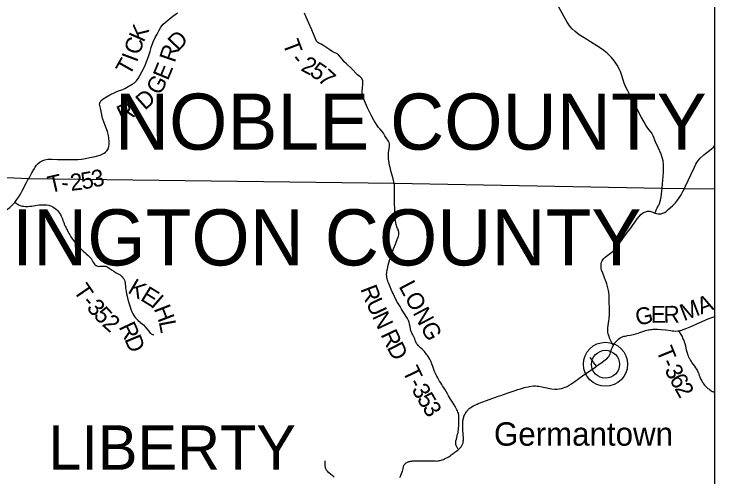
# Model space of a CAD drawing. Extents: x -10.5 to 40.6, y -3.2 to 22.
# Drawn here: x -6.111 to -3.744, y 15.878 to 17.441 of the extents above; entities that cross this region are included whole.
import ezdxf

# ---------------------------------------------------------------- set-up
doc = ezdxf.new("R2010")
doc.units = 0
for name, color, linetype in [('GM_X_County_Road', 7, 'Continuous'), ('GM_X_County_Road_Text', 7, 'Continuous'), ('GM_X_County_Text', 7, 'Continuous'), ('GM_X_Township_Road', 7, 'Continuous'), ('GM_X_Township_Road_Text', 7, 'Continuous'), ('GM_X_Township_Text', 7, 'Continuous'), ('GM_X_Unincorporated', 7, 'Continuous'), ('GM_X_Unincorporated_Location', 7, 'Continuous'), ('GM_X_Unincorporated_Text', 7, 'Continuous')]:
    doc.layers.add(name, color=color, linetype=linetype)

msp = doc.modelspace()

# ---------------------------------------------------------------- linework, layer by layer
at = {"layer": 'GM_X_County_Road'}
for points in [[(-3.9229, 16.8524), (-3.9187, 16.9064), (-3.9181, 16.9318), (-3.9195, 16.9446), (-3.9213, 16.9525), (-3.9266, 16.9678), (-3.9363, 16.9905), (-3.9448, 17.0094), (-3.9535, 17.0299), (-3.9578, 17.0378), (-3.9626, 17.0445), (-3.9708, 17.0557), (-3.9776, 17.0657), (-3.9852, 17.0778), (-3.9923, 17.0907), (-4.0218, 17.148), (-4.0293, 17.1627), (-4.0388, 17.1811), (-4.0461, 17.1958), (-4.051, 17.2067), (-4.0546, 17.2183), (-4.0611, 17.2399), (-4.0636, 17.247), (-4.0669, 17.2535), (-4.0749, 17.2681), (-4.0839, 17.2813), (-4.0938, 17.2934), (-4.1099, 17.3092), (-4.1247, 17.3213), (-4.1432, 17.3335), (-4.1652, 17.3472), (-4.186, 17.3599), (-4.2034, 17.3705), (-4.2103, 17.3758), (-4.2167, 17.3811), (-4.2264, 17.3905), (-4.2341, 17.3999), (-4.2431, 17.4125), (-4.2536, 17.4307), (-4.2776, 17.4736)], [(-3.8479, 16.8511), (-3.8436, 16.8597), (-3.8262, 16.8978), (-3.8138, 16.9239), (-3.8088, 16.9339), (-3.8054, 16.9396), (-3.8005, 16.9469), (-3.7942, 16.9542), (-3.7825, 16.9647), (-3.7577, 16.984), (-3.749, 16.9916), (-3.7445, 16.9965)], [(-3.9472, 16.7684), (-3.9468, 16.7693), (-3.9429, 16.7783), (-3.9414, 16.7819), (-3.9392, 16.7866), (-3.9379, 16.7892), (-3.9362, 16.7922), (-3.9347, 16.7951), (-3.9334, 16.7977), (-3.932, 16.8013), (-3.9312, 16.8036), (-3.9305, 16.8059), (-3.9288, 16.8118), (-3.9265, 16.8221), (-3.9248, 16.8325), (-3.9238, 16.8436), (-3.9229, 16.8524)], [(-3.9472, 16.7684), (-3.9418, 16.767), (-3.9364, 16.7662), (-3.9309, 16.7661), (-3.9267, 16.7665), (-3.9214, 16.7678), (-3.9174, 16.7692), (-3.9142, 16.7709), (-3.9087, 16.7747), (-3.9021, 16.7802), (-3.8881, 16.7934), (-3.8782, 16.8037), (-3.8706, 16.8126), (-3.8651, 16.82), (-3.8588, 16.8299), (-3.8527, 16.8414), (-3.8479, 16.8511)], [(-4.0877, 16.3218), (-4.0894, 16.3242), (-4.0927, 16.3301), (-4.0966, 16.3374), (-4.0985, 16.3418), (-4.1005, 16.3468), (-4.1023, 16.3524), (-4.1038, 16.357), (-4.1049, 16.3612), (-4.1058, 16.3655), (-4.1065, 16.3709), (-4.1065, 16.376), (-4.1063, 16.3817), (-4.1054, 16.3885), (-4.1026, 16.4051), (-4.1017, 16.4111), (-4.1012, 16.4173), (-4.1009, 16.4228), (-4.1005, 16.4284), (-4.1004, 16.4445), (-4.1012, 16.4712), (-4.1021, 16.4904), (-4.1031, 16.5015), (-4.1038, 16.5071), (-4.1048, 16.5119), (-4.1058, 16.516), (-4.1069, 16.5209), (-4.1097, 16.5297), (-4.1143, 16.5419), (-4.1165, 16.5471), (-4.119, 16.5533), (-4.1236, 16.5655), (-4.1271, 16.5763), (-4.1286, 16.583), (-4.1291, 16.5887), (-4.129, 16.5938), (-4.1283, 16.5988), (-4.1272, 16.6031), (-4.1254, 16.6073), (-4.1231, 16.6111), (-4.1207, 16.614), (-4.1183, 16.6168), (-4.1149, 16.6198), (-4.1012, 16.6295), (-4.0925, 16.6364), (-4.0871, 16.6414), (-4.0824, 16.6463), (-4.0754, 16.6549), (-4.0685, 16.6644), (-4.0553, 16.6833), (-4.04, 16.7036), (-4.0267, 16.7215), (-4.0234, 16.7261), (-4.0144, 16.7387), (-4.0071, 16.7487), (-3.9998, 16.758), (-3.9947, 16.7636), (-3.9905, 16.7674), (-3.9862, 16.7702), (-3.9828, 16.7718), (-3.9785, 16.7733), (-3.9729, 16.7745), (-3.9679, 16.7749), (-3.9643, 16.7748), (-3.9608, 16.774), (-3.9579, 16.7728), (-3.9545, 16.7711), (-3.9472, 16.7684)], [(-3.8687, 16.3709), (-3.8635, 16.3717), (-3.8601, 16.3724), (-3.8564, 16.3736), (-3.8524, 16.375), (-3.8489, 16.3763), (-3.8391, 16.3802), (-3.8231, 16.3871), (-3.8033, 16.3958), (-3.7879, 16.4025), (-3.7759, 16.4078), (-3.7616, 16.4138), (-3.7488, 16.4188), (-3.7445, 16.4203)], [(-4.0877, 16.3218), (-4.0872, 16.3228), (-4.0832, 16.3292), (-4.0782, 16.3356), (-4.0738, 16.3401), (-4.0689, 16.3442), (-4.0648, 16.3471), (-4.0603, 16.3495), (-4.0572, 16.3508), (-4.0544, 16.3518), (-4.0517, 16.3525), (-4.0481, 16.3532), (-4.0426, 16.3545), (-4.0406, 16.3549)], [(-4.0406, 16.3549), (-4.0306, 16.3567), (-4.0253, 16.3577), (-4.0194, 16.3592), (-4.0121, 16.3613), (-4.0041, 16.3637), (-3.9981, 16.3658), (-3.9911, 16.3682), (-3.9817, 16.3713), (-3.9787, 16.3721), (-3.9746, 16.3731), (-3.9704, 16.374), (-3.9667, 16.3746), (-3.9619, 16.3754), (-3.9585, 16.3759), (-3.9548, 16.3763), (-3.9487, 16.3767), (-3.9435, 16.3769), (-3.9386, 16.3768), (-3.9268, 16.3759), (-3.9101, 16.3739), (-3.8941, 16.3717), (-3.8892, 16.3711), (-3.8843, 16.3705), (-3.8769, 16.3703), (-3.8696, 16.3707), (-3.8687, 16.3709)], [(-4.1442, 16.2516), (-4.1385, 16.2558), (-4.1304, 16.2619), (-4.1111, 16.2763), (-4.1088, 16.278), (-4.1066, 16.2805), (-4.1049, 16.2821), (-4.103, 16.2845), (-4.1019, 16.2862), (-4.1005, 16.2887), (-4.0995, 16.2906), (-4.0985, 16.2932), (-4.0957, 16.302), (-4.0934, 16.3091), (-4.0908, 16.3155), (-4.0877, 16.3218)], [(-4.6107, 15.9708), (-4.6093, 15.9718), (-4.6048, 15.9759), (-4.6016, 15.9796), (-4.6, 15.9816), (-4.5989, 15.9835), (-4.5976, 15.9859), (-4.5966, 15.9886), (-4.5958, 15.9908), (-4.5951, 15.9934), (-4.5946, 15.9961), (-4.5944, 15.9986), (-4.594, 16.0016), (-4.5939, 16.0096), (-4.5944, 16.0201), (-4.5955, 16.0406), (-4.5957, 16.0462), (-4.5959, 16.0537), (-4.5956, 16.0637), (-4.5953, 16.0671), (-4.5948, 16.0705), (-4.5946, 16.0728), (-4.5939, 16.0759), (-4.593, 16.0792), (-4.592, 16.0818), (-4.5908, 16.0849), (-4.5891, 16.0885), (-4.5877, 16.0915), (-4.5858, 16.0946), (-4.5839, 16.0978), (-4.582, 16.1003), (-4.5803, 16.1023), (-4.5782, 16.1046), (-4.5764, 16.1065), (-4.5741, 16.1085), (-4.5715, 16.1106), (-4.5686, 16.1127), (-4.5654, 16.1149), (-4.5612, 16.1175), (-4.5573, 16.1195), (-4.5528, 16.1217), (-4.5477, 16.1239), (-4.5441, 16.1254), (-4.5402, 16.1271), (-4.5157, 16.1363), (-4.494, 16.144), (-4.4844, 16.1474), (-4.4764, 16.1502), (-4.4677, 16.1533), (-4.443, 16.1617), (-4.4294, 16.1661), (-4.4188, 16.1697), (-4.4107, 16.1725), (-4.4011, 16.1757), (-4.3939, 16.1778), (-4.3879, 16.1794), (-4.3825, 16.1809), (-4.3758, 16.1822), (-4.3702, 16.1833), (-4.3653, 16.1841), (-4.3572, 16.185), (-4.354, 16.1851), (-4.3503, 16.185), (-4.3453, 16.1848), (-4.3391, 16.1839), (-4.3293, 16.182), (-4.3184, 16.1795), (-4.3117, 16.1782), (-4.3072, 16.1773), (-4.302, 16.1764), (-4.2953, 16.1753), (-4.2854, 16.1743), (-4.2775, 16.1742), (-4.2701, 16.1749), (-4.2629, 16.1763), (-4.2564, 16.1782), (-4.2501, 16.1805), (-4.2433, 16.1836), (-4.24, 16.1852), (-4.2368, 16.1871), (-4.2295, 16.1917), (-4.2165, 16.2011), (-4.2095, 16.2062), (-4.2026, 16.2111), (-4.1961, 16.2157), (-4.1873, 16.222), (-4.1651, 16.237), (-4.1473, 16.2493), (-4.1442, 16.2516)], [(-4.809, 15.8762), (-4.8054, 15.8827), (-4.8026, 15.8894), (-4.8001, 15.8977), (-4.7967, 15.911), (-4.7957, 15.9137), (-4.7946, 15.9163), (-4.7934, 15.9184), (-4.7923, 15.9202), (-4.7908, 15.922), (-4.789, 15.9236), (-4.7872, 15.9251), (-4.785, 15.9265), (-4.7829, 15.9277), (-4.7806, 15.9287), (-4.7777, 15.9296), (-4.7752, 15.9302), (-4.772, 15.9309), (-4.7684, 15.9315), (-4.7643, 15.9318), (-4.7568, 15.9323), (-4.745, 15.9325), (-4.7313, 15.9327), (-4.712, 15.9321), (-4.6953, 15.9317), (-4.6889, 15.9318), (-4.6854, 15.9316), (-4.6814, 15.9319), (-4.6787, 15.9322), (-4.6756, 15.9328), (-4.6727, 15.9335), (-4.6686, 15.9346), (-4.6655, 15.9355), (-4.6616, 15.937), (-4.6582, 15.9385), (-4.655, 15.9399), (-4.651, 15.9419), (-4.6472, 15.9439), (-4.6435, 15.9462), (-4.6387, 15.9494), (-4.6348, 15.9521), (-4.6283, 15.9571), (-4.6225, 15.9615), (-4.6161, 15.9665), (-4.6107, 15.9708)]]:
    msp.add_lwpolyline(points, dxfattribs=at)
at = {"layer": 'GM_X_Township_Road'}
for points in [[(-6.0618, 16.8853), (-6.0591, 16.8892), (-6.0512, 16.9046), (-6.0448, 16.9161), (-6.0402, 16.9235), (-6.0353, 16.93), (-6.0301, 16.9356), (-6.0234, 16.9413), (-6.0189, 16.9441), (-6.0142, 16.9465), (-6.0071, 16.9487), (-5.9967, 16.9504), (-5.9831, 16.9508), (-5.9646, 16.95), (-5.9443, 16.9498), (-5.9275, 16.9491), (-5.9167, 16.9489), (-5.9072, 16.9491), (-5.8962, 16.9494), (-5.8832, 16.9508), (-5.8695, 16.9526), (-5.8554, 16.9557), (-5.8413, 16.9589), (-5.8209, 16.9644), (-5.8067, 16.9704), (-5.8021, 16.9739), (-5.7978, 16.9784), (-5.7931, 16.9857), (-5.7913, 16.9935), (-5.7904, 17.0025), (-5.7904, 17.0105), (-5.7906, 17.0211), (-5.792, 17.0304), (-5.7959, 17.0443), (-5.807, 17.0733), (-5.8124, 17.0887), (-5.8157, 17.1056), (-5.8184, 17.1177), (-5.8207, 17.1272), (-5.8216, 17.1318), (-5.8221, 17.1368), (-5.8208, 17.1425), (-5.8181, 17.1475), (-5.8099, 17.1537), (-5.7872, 17.1672), (-5.7712, 17.1758), (-5.7586, 17.1808), (-5.7477, 17.1848), (-5.7371, 17.1896), (-5.7253, 17.1959), (-5.712, 17.2034), (-5.7048, 17.2086), (-5.698, 17.2153), (-5.6921, 17.2232), (-5.6864, 17.2326), (-5.6729, 17.2573), (-5.6676, 17.2702), (-5.6564, 17.3009), (-5.6516, 17.3143), (-5.648, 17.3271), (-5.641, 17.3468), (-5.6344, 17.3615), (-5.6284, 17.3725), (-5.6221, 17.3836), (-5.6153, 17.3963), (-5.6071, 17.406), (-5.6014, 17.4118), (-5.5874, 17.4236), (-5.5753, 17.4333), (-5.5593, 17.4446)], [(-4.8272, 16.8687), (-4.8283, 16.8743), (-4.8311, 16.8847), (-4.8376, 16.9082), (-4.8416, 16.9223), (-4.843, 16.9296), (-4.8451, 16.9398), (-4.8467, 16.952), (-4.8465, 16.973), (-4.8451, 16.9859), (-4.8433, 16.9963), (-4.8439, 17.0021), (-4.845, 17.0066), (-4.847, 17.0108), (-4.8544, 17.0222), (-4.8589, 17.0295), (-4.8641, 17.0384), (-4.8686, 17.0441), (-4.8755, 17.0514), (-4.8802, 17.0574), (-4.8949, 17.0795), (-4.9044, 17.0963), (-4.9173, 17.1239), (-4.9311, 17.1559), (-4.9339, 17.1632), (-4.9356, 17.1689), (-4.9358, 17.1738), (-4.9357, 17.1789), (-4.9343, 17.1918), (-4.9334, 17.2022), (-4.9333, 17.2096), (-4.9337, 17.2152), (-4.9369, 17.2228), (-4.9425, 17.2283), (-4.951, 17.235), (-4.9722, 17.2569), (-4.989, 17.2726), (-4.996, 17.2797), (-5.0027, 17.287), (-5.009, 17.2954), (-5.0157, 17.3031), (-5.0226, 17.3072), (-5.0302, 17.3107), (-5.0366, 17.3142), (-5.0451, 17.3194), (-5.0647, 17.3333), (-5.0738, 17.3388), (-5.0815, 17.3419), (-5.0869, 17.345), (-5.0902, 17.3492), (-5.0932, 17.3565), (-5.1056, 17.3874), (-5.1153, 17.41), (-5.1244, 17.4304), (-5.1306, 17.443)], [(-6.1085, 16.8045), (-6.1059, 16.8076), (-6.1012, 16.8141), (-6.0948, 16.8238), (-6.0893, 16.8327), (-6.0833, 16.8434), (-6.078, 16.8538), (-6.0731, 16.8638), (-6.0689, 16.872), (-6.0618, 16.8853)], [(-4.6107, 15.9708), (-4.6122, 15.9732), (-4.6164, 15.9798), (-4.6181, 15.9838), (-4.6191, 15.9873), (-4.6197, 15.9916), (-4.6197, 15.9952), (-4.619, 15.9995), (-4.6176, 16.0056), (-4.616, 16.0114), (-4.6133, 16.0223), (-4.6121, 16.0271), (-4.6113, 16.032), (-4.6106, 16.0381), (-4.6101, 16.0433), (-4.6098, 16.0493), (-4.6095, 16.0648), (-4.6095, 16.074), (-4.6094, 16.0803), (-4.6099, 16.0871), (-4.6102, 16.0899), (-4.611, 16.0926), (-4.6123, 16.0967), (-4.6143, 16.101), (-4.6157, 16.104), (-4.6202, 16.1129), (-4.6251, 16.1208), (-4.631, 16.1304), (-4.6372, 16.1403), (-4.6439, 16.152), (-4.6478, 16.1586), (-4.652, 16.1659), (-4.6565, 16.1736), (-4.6612, 16.1809), (-4.6642, 16.1851), (-4.6671, 16.1897), (-4.6706, 16.1953), (-4.6742, 16.2012), (-4.6807, 16.2125), (-4.6837, 16.218), (-4.6861, 16.223), (-4.6883, 16.2275), (-4.691, 16.2337), (-4.6936, 16.2405), (-4.6964, 16.2476), (-4.701, 16.2594), (-4.7044, 16.2684), (-4.7078, 16.2758), (-4.7109, 16.2812), (-4.7142, 16.2862), (-4.7173, 16.2903), (-4.7197, 16.2938), (-4.7228, 16.2978), (-4.7257, 16.3012), (-4.7284, 16.3044), (-4.7337, 16.3096), (-4.7388, 16.314), (-4.7427, 16.3172), (-4.7467, 16.321), (-4.7494, 16.3244), (-4.752, 16.3285), (-4.7546, 16.3341), (-4.7566, 16.3387), (-4.7584, 16.3438), (-4.7605, 16.3489), (-4.7628, 16.3534), (-4.7648, 16.3574), (-4.7667, 16.3605), (-4.7694, 16.3661), (-4.7705, 16.3693), (-4.7715, 16.3719), (-4.773, 16.3779), (-4.7742, 16.3855), (-4.7757, 16.3932), (-4.7774, 16.3998), (-4.7794, 16.4057), (-4.7807, 16.4086), (-4.7826, 16.4124), (-4.7847, 16.4156), (-4.7867, 16.4194), (-4.7906, 16.425), (-4.7955, 16.4322), (-4.7993, 16.4383), (-4.8028, 16.4439), (-4.8078, 16.4528), (-4.8159, 16.4669), (-4.8217, 16.4773), (-4.8269, 16.4871), (-4.8316, 16.4966), (-4.8345, 16.5026), (-4.8376, 16.5102), (-4.8417, 16.5194), (-4.8461, 16.5309), (-4.8478, 16.5353), (-4.8494, 16.5403), (-4.8508, 16.5444), (-4.8515, 16.548), (-4.8522, 16.5521), (-4.8527, 16.5554), (-4.8531, 16.5613), (-4.8529, 16.5666), (-4.8524, 16.5698), (-4.8518, 16.5751), (-4.8505, 16.5806), (-4.8476, 16.5927), (-4.8432, 16.6083), (-4.8365, 16.6283), (-4.8294, 16.6479), (-4.8234, 16.6638), (-4.816, 16.6829), (-4.8144, 16.6866), (-4.8133, 16.6905), (-4.8124, 16.6948), (-4.8118, 16.6997), (-4.8119, 16.7041), (-4.8126, 16.7077), (-4.8136, 16.7106), (-4.8159, 16.7167), (-4.8182, 16.7227), (-4.8209, 16.7303), (-4.8223, 16.7357), (-4.8236, 16.743), (-4.8244, 16.7529), (-4.8248, 16.7647), (-4.8252, 16.7755), (-4.8255, 16.7845), (-4.8266, 16.7994), (-4.827, 16.8106), (-4.827, 16.8224), (-4.8269, 16.8303), (-4.8268, 16.8397), (-4.8264, 16.8495), (-4.8264, 16.8558), (-4.8267, 16.8648), (-4.8272, 16.8687)], [(-6.1833, 16.7482), (-6.1829, 16.7492), (-6.1826, 16.7497), (-6.1798, 16.7537), (-6.177, 16.7567), (-6.174, 16.7591), (-6.1702, 16.7617), (-6.1648, 16.7649), (-6.157, 16.7691), (-6.1469, 16.7741), (-6.1334, 16.7819), (-6.1255, 16.7875), (-6.1207, 16.7918), (-6.1154, 16.797), (-6.1103, 16.8024), (-6.1085, 16.8045)], [(-6.1085, 16.8045), (-6.1043, 16.8017), (-6.1007, 16.7994), (-6.0959, 16.7968), (-6.0904, 16.7943), (-6.087, 16.7931), (-6.0828, 16.7921), (-6.0785, 16.7914), (-6.0729, 16.7911), (-6.0649, 16.7911), (-6.0574, 16.7915), (-6.0506, 16.7921), (-6.0396, 16.7938), (-6.0329, 16.795), (-6.0261, 16.796), (-6.0193, 16.7967), (-6.0125, 16.7969), (-6.0058, 16.7966), (-6.0002, 16.796), (-5.9942, 16.7948), (-5.9882, 16.7931), (-5.9842, 16.7917), (-5.9803, 16.7898), (-5.9766, 16.7875), (-5.9721, 16.7842), (-5.9683, 16.7809), (-5.9648, 16.7774), (-5.9612, 16.7732), (-5.9576, 16.7682), (-5.9546, 16.7635), (-5.9516, 16.7582), (-5.9496, 16.7538), (-5.9479, 16.7493), (-5.946, 16.7435), (-5.9447, 16.7394), (-5.9436, 16.7365), (-5.9423, 16.733), (-5.9414, 16.7307), (-5.9382, 16.724), (-5.9365, 16.7207), (-5.9325, 16.7129), (-5.9288, 16.7051), (-5.9263, 16.7), (-5.9232, 16.6947), (-5.9189, 16.6879), (-5.9136, 16.6803), (-5.9073, 16.672), (-5.9017, 16.6648), (-5.897, 16.6593), (-5.8913, 16.6531), (-5.8858, 16.6476), (-5.8796, 16.6418), (-5.8778, 16.6401), (-5.8716, 16.635), (-5.8671, 16.6307), (-5.8605, 16.6249), (-5.8564, 16.6211), (-5.8535, 16.6179), (-5.8513, 16.615), (-5.8484, 16.6102), (-5.845, 16.6043), (-5.8419, 16.5997), (-5.8392, 16.5963), (-5.8367, 16.5936), (-5.8343, 16.5916), (-5.8316, 16.5901), (-5.8287, 16.5891), (-5.8257, 16.5887), (-5.822, 16.5888), (-5.8127, 16.5898), (-5.8083, 16.5899), (-5.8034, 16.5894), (-5.801, 16.5889), (-5.7981, 16.5878), (-5.7948, 16.5861), (-5.7902, 16.583), (-5.7802, 16.5757), (-5.7781, 16.5742), (-5.775, 16.5723), (-5.7729, 16.571), (-5.7719, 16.5702), (-5.7692, 16.5687), (-5.7665, 16.5672), (-5.7534, 16.56), (-5.7503, 16.558), (-5.748, 16.556), (-5.7455, 16.5533), (-5.7433, 16.5503), (-5.7408, 16.5461), (-5.7387, 16.5417), (-5.7372, 16.5377), (-5.7363, 16.5341), (-5.7356, 16.5293), (-5.7351, 16.522), (-5.7348, 16.5152), (-5.7341, 16.5103), (-5.7329, 16.5036), (-5.7313, 16.4957), (-5.7295, 16.4878), (-5.7265, 16.4765), (-5.7235, 16.4658), (-5.7193, 16.4521), (-5.7165, 16.4439), (-5.7131, 16.4353), (-5.71, 16.4286), (-5.7071, 16.4232), (-5.7044, 16.419), (-5.7014, 16.4152), (-5.698, 16.4116), (-5.6929, 16.407), (-5.6838, 16.3996), (-5.6771, 16.3941), (-5.6739, 16.3911), (-5.6685, 16.3851), (-5.6626, 16.3779), (-5.6566, 16.37), (-5.6515, 16.3637), (-5.6493, 16.3615), (-5.6478, 16.3605), (-5.6461, 16.3598), (-5.6437, 16.3592), (-5.64, 16.3587), (-5.6388, 16.3585)], [(-3.8687, 16.3709), (-3.8667, 16.3683), (-3.8634, 16.3641), (-3.8616, 16.3615), (-3.8595, 16.3585), (-3.8574, 16.355), (-3.8556, 16.3515), (-3.8537, 16.3476), (-3.8525, 16.3445), (-3.8515, 16.3421), (-3.8499, 16.3379), (-3.8483, 16.3334), (-3.8468, 16.3282), (-3.8445, 16.3199), (-3.8426, 16.3122), (-3.8414, 16.307), (-3.8398, 16.3005), (-3.8388, 16.2969), (-3.8375, 16.2924), (-3.8365, 16.2896), (-3.835, 16.2861), (-3.8335, 16.2826), (-3.8318, 16.2796), (-3.8299, 16.2759), (-3.827, 16.2711), (-3.8248, 16.2674), (-3.8221, 16.2633), (-3.8182, 16.2576), (-3.8141, 16.2515), (-3.8106, 16.2466), (-3.8069, 16.2414), (-3.8037, 16.2361), (-3.8011, 16.2305), (-3.7992, 16.2257), (-3.7976, 16.2205), (-3.7957, 16.2153), (-3.793, 16.2091), (-3.7913, 16.2058), (-3.7892, 16.202), (-3.7873, 16.1986), (-3.7849, 16.1951), (-3.783, 16.1923), (-3.7798, 16.1881), (-3.776, 16.184), (-3.7736, 16.1814), (-3.7704, 16.1785), (-3.7683, 16.1769), (-3.7657, 16.1747), (-3.7628, 16.1727), (-3.7595, 16.1704), (-3.757, 16.1687), (-3.7536, 16.1668), (-3.7518, 16.166), (-3.7497, 16.1651), (-3.7477, 16.1644), (-3.7452, 16.1637), (-3.7445, 16.1635)], [(-4.1442, 16.2516), (-4.1448, 16.2523), (-4.1542, 16.2646), (-4.1573, 16.2691), (-4.1616, 16.2752), (-4.1655, 16.2807)], [(-5.0305, 15.8773), (-5.0345, 15.8812), (-5.0413, 15.8866), (-5.0494, 15.8933), (-5.0529, 15.8969), (-5.0544, 15.8988), (-5.0559, 15.9009), (-5.0579, 15.9047), (-5.059, 15.9076), (-5.0601, 15.9117), (-5.0606, 15.9146), (-5.0608, 15.9171), (-5.0608, 15.9192), (-5.0606, 15.9227), (-5.0604, 15.9264), (-5.0603, 15.9295), (-5.0602, 15.9319)]]:
    msp.add_lwpolyline(points, dxfattribs=at)
at = {"layer": 'GM_X_Township_Text'}
for points in [[(-3.7445, 16.8499), (-3.7445, 20.9), (-6.1618, 20.9)], [(-6.1874, 16.891), (-6.1985, 16.7494), (-6.1956, 16.4198), (-6.1883, 16.2366), (-6.1993, 15.3843), (-6.2122, 14.1), (-3.7445, 14.1), (-3.7445, 16.8499)], [(-6.1874, 16.891), (-6.062, 16.8858), (-4.8274, 16.8692), (-3.9231, 16.8529), (-3.8481, 16.8517), (-3.7445, 16.8499)]]:
    msp.add_lwpolyline(points, dxfattribs=at)
at = {"layer": 'GM_X_Unincorporated'}
for radius in [0.0744, 0.0472]:
    msp.add_circle((-4.1142, 16.2582), radius, dxfattribs=at)
at = {"layer": 'GM_X_Unincorporated_Location'}
msp.add_line((-4.1142, 16.2582), (-4.1142, 16.2582), dxfattribs=at)

# ---------------------------------------------------------------- texts
at = {"layer": 'GM_X_County_Road_Text'}
for s, rotation, p in [('M', 21.2453, (-3.8495, 16.4031)), ('A', 21.0336, (-3.7921, 16.4254)), ('G', 12.3388, (-4.0067, 16.388)), ('E', 0.06, (-3.9611, 16.3984)), ('R', 0.5745, (-3.918, 16.3984))]:
    msp.add_text(s, height=0.0568, rotation=rotation, dxfattribs=at).set_placement(p)
at = {"layer": 'GM_X_County_Text'}
for s, p in [('NOBLE COUNTY', (-5.7706, 16.9826)), ('WASHINGTON COUNTY', (-6.8771, 16.5918))]:
    msp.add_text(s, height=0.189394, dxfattribs=at).set_placement(p)
at = {"layer": 'GM_X_Township_Road_Text'}
for s, height, rotation, p in [('K', 0.0568, 66.026, (-5.6738, 17.3424)), ('D', 0.0568, 46.3679, (-5.5569, 17.3127)), ('C', 0.0568, 71.9979, (-5.6876, 17.2995)), ('T', 0.0568, 290.8575, (-5.2055, 17.3418)), ('R', 0.0568, 71.2281, (-5.5686, 17.274)), ('I', 0.0568, 69.5138, (-5.6967, 17.2751)), ('T', 0.0568, 60.5916, (-5.7216, 17.2293)), ('E', 0.0568, 67.5914, (-5.5918, 17.2136)), ('-', 0.0568, 309.7066, (-5.1802, 17.2845)), ('2', 0.0568, 332.789, (-5.1459, 17.2511)), ('5', 0.0568, 325.8394, (-5.1164, 17.236)), ('7', 0.0568, 317.9451, (-5.089, 17.2176)), ('G', 0.0568, 61.2786, (-5.6187, 17.1635)), ('D', 0.0568, 41.5116, (-5.6695, 17.1137)), ('R', 0.0568, 25.0864, (-5.7473, 17.0735)), ('I', 0.0568, 27.4269, (-5.7027, 17.0944)), ('T', 0.0568, 12.9011, (-5.9902, 16.8358)), ('2', 0.0568, 6.1608, (-5.919, 16.8436)), ('5', 0.0568, 10.0444, (-5.8801, 16.8479)), ('3', 0.0568, 12.3046, (-5.8432, 16.8545)), ('-', 0.0568, 356.1018, (-5.9532, 16.845)), ('K', 0.0568, 329.323, (-5.7305, 16.5016)), ('T', 0.0568, 304.3569, (-5.9131, 16.5064)), ('E', 0.0568, 328.5166, (-5.6877, 16.4762)), ('R', 0.0568, 291.1549, (-4.9427, 16.5127)), ('LONG', 0.05682, 297.8588, (-4.8134, 16.5217)), ('-', 0.0568, 310.7667, (-5.8849, 16.4658)), ('3', 0.0568, 312.0621, (-5.8688, 16.4471)), ('I', 0.0568, 318.7451, (-5.6535, 16.4555)), ('U', 0.0568, 295.1026, (-4.9242, 16.4653)), ('5', 0.0568, 312.3605, (-5.8451, 16.4209)), ('H', 0.0568, 291.1453, (-5.6401, 16.446)), ('N', 0.0568, 295.1561, (-4.903, 16.42)), ('2', 0.0568, 318.6934, (-5.8166, 16.3902)), ('R', 0.0568, 295.0131, (-5.7587, 16.3848)), ('L', 0.0568, 280.6644, (-5.6228, 16.402)), ('D', 0.0568, 292.5036, (-5.7392, 16.3431)), ('R', 0.0568, 295.217, (-4.8743, 16.3588)), ('D', 0.0568, 297.3139, (-4.8534, 16.3146)), ('T', 0.0568, 291.9705, (-3.9438, 16.3057)), ('-', 0.0568, 292.9483, (-3.9276, 16.2653)), ('T', 0.0568, 295.7198, (-4.801, 16.2356)), ('3', 0.0568, 297.7959, (-3.9163, 16.2393)), ('6', 0.0568, 298.68, (-3.8996, 16.2078)), ('3', 0.0568, 299.0879, (-4.7702, 16.1734)), ('-', 0.0568, 297.4802, (-4.7817, 16.1956)), ('2', 0.0568, 299.7137, (-3.8824, 16.1763)), ('5', 0.0568, 300.4226, (-4.7524, 16.1416)), ('3', 0.0568, 301.1229, (-4.7343, 16.1107))]:
    msp.add_text(s, height=height, rotation=rotation, dxfattribs=at).set_placement(p)
at = {"layer": 'GM_X_Township_Text'}
msp.add_text('LIBERTY', height=0.15, rotation=0, dxfattribs=at).set_placement((-5.9953, 15.9021))
at = {"layer": 'GM_X_Unincorporated_Text'}
msp.add_text('Germantown', height=0.07898, rotation=0, dxfattribs=at).set_placement((-4.4908, 15.9833))

doc.saveas('drawing.dxf')
